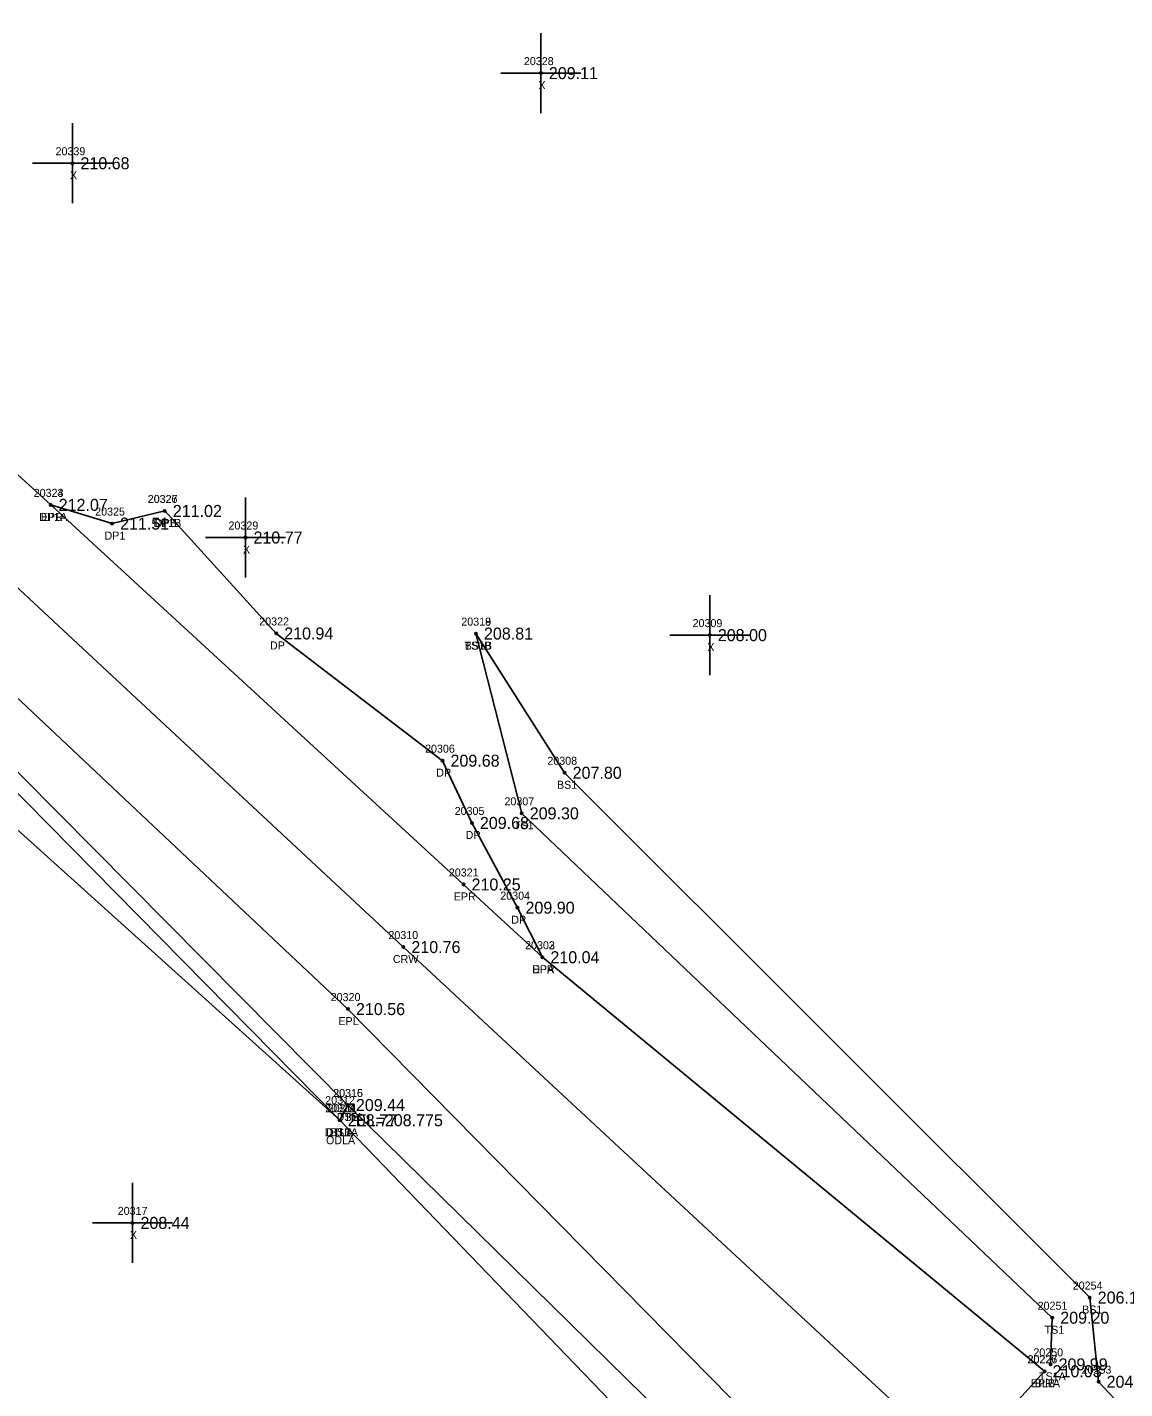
# Model space of a CAD drawing. Extents: x 2260230 to 2261304, y 1064626 to 1065587.
# Drawn here: x 2260344.2 to 2260481.3, y 1065386.5 to 1065556.6 of the extents above; entities that cross this region are included whole.
import ezdxf

# ---------------------------------------------------------------- set-up
doc = ezdxf.new("R2010")
doc.units = 0
for name, color, linetype in [('RD_DTM_BkLn1', 7, 'Continuous'), ('RD_DTM_BkLn2', 7, 'Continuous'), ('RD_DTM_BkLn_txCode', 7, 'Continuous'), ('RD_EX_Driveway', 7, 'Continuous'), ('RD_EX_Driveway_txCode', 7, 'Continuous'), ('RD_EX_H2O', 7, 'Continuous'), ('RD_EX_H2O_txCode', 7, 'Continuous'), ('RD_EX_Misc', 7, 'Continuous'), ('RD_EX_Misc_txCode', 7, 'Continuous'), ('RD_EX_Road', 7, 'Continuous'), ('RD_EX_Road_txCode', 7, 'Continuous'), ('RD_EX_TX_Driveway_ELEV', 7, 'Continuous'), ('RD_EX_TX_H2O_ELEV', 7, 'Continuous'), ('RD_EX_TX_Misc_ELEV', 7, 'Continuous'), ('RD_EX_TX_Road_ELEV', 7, 'Continuous'), ('RD_HC_Survey_ELEV', 7, 'Continuous'), ('RD_HC_Survey_txCode', 7, 'Continuous'), ('RD_SMD_Locator', 7, 'Continuous')]:
    doc.layers.add(name, color=color, linetype=linetype)

msp = doc.modelspace()

# ---------------------------------------------------------------- linework, layer by layer
at = {"layer": 'RD_DTM_BkLn1'}
for points in [[(2260460.75, 1065377.06), (2260391.17, 1065441.67), (2260322.55, 1065505.55), (2260275.44, 1065548.93)], [(2260450.76, 1065366.34), (2260460.75, 1065377.06), (2260471.29, 1065388.66)]]:
    msp.add_lwpolyline(points, dxfattribs=at)
at = {"layer": 'RD_DTM_BkLn2'}
for points in [[(2260472.04, 1065389.52), (2260472.25, 1065395.35), (2260405.96, 1065458.38), (2260400.24, 1065480.84)], [(2260484.22, 1065380.75), (2260478.04, 1065387.35), (2260476.93, 1065397.87), (2260411.32, 1065463.45), (2260400.24, 1065480.84)], [(2260448.41, 1065364.08), (2260444.54, 1065362.67), (2260384.24, 1065421.93)], [(2260459.63, 1065339.19), (2260441.77, 1065357.68), (2260430.08, 1065371.39), (2260383.23, 1065420.03)]]:
    msp.add_lwpolyline(points, dxfattribs=at)
at = {"layer": 'RD_EX_Driveway'}
for points in [[(2260347.1, 1065496.93), (2260354.77, 1065494.59), (2260361.36, 1065496.17)], [(2260408.54, 1065440.4), (2260405.43, 1065446.59), (2260399.73, 1065457.18), (2260396.06, 1065464.96), (2260375.28, 1065480.86), (2260361.36, 1065496.17)]]:
    msp.add_lwpolyline(points, dxfattribs=at)
at = {"layer": 'RD_EX_H2O'}
for points in [[(2260383.23, 1065420.03), (2260384.24, 1065421.93), (2260311.81, 1065494.98), (2260265.21, 1065536.25)], [(2260383.23, 1065420.03), (2260310.39, 1065493.94), (2260264.03, 1065534.75)], [(2260383.23, 1065420.03), (2260328.98, 1065468.86), (2260307.44, 1065488.32), (2260261.06, 1065532)]]:
    msp.add_lwpolyline(points, dxfattribs=at)
at = {"layer": 'RD_EX_Misc'}
for p, q in [((2260408.35, 1065545.88), (2260408.35, 1065555.88)), ((2260403.35, 1065550.88), (2260413.35, 1065550.88)), ((2260349.82, 1065534.62), (2260349.82, 1065544.62)), ((2260344.82, 1065539.62), (2260354.82, 1065539.62)), ((2260371.44, 1065487.85), (2260371.44, 1065497.85)), ((2260366.44, 1065492.85), (2260376.44, 1065492.85)), ((2260429.46, 1065475.65), (2260429.46, 1065485.65)), ((2260424.46, 1065480.65), (2260434.46, 1065480.65)), ((2260357.32, 1065402.2), (2260357.32, 1065412.2)), ((2260352.32, 1065407.2), (2260362.32, 1065407.2))]:
    msp.add_line(p, q, dxfattribs=at)
at = {"layer": 'RD_EX_Road'}
for points in [[(2260471.29, 1065388.66), (2260408.54, 1065440.4), (2260398.69, 1065449.49), (2260347.1, 1065496.93), (2260329.06, 1065513.35), (2260281.81, 1065556.62)], [(2260450.76, 1065366.34), (2260384.25, 1065433.92), (2260316.12, 1065498), (2260269.16, 1065540.98)]]:
    msp.add_lwpolyline(points, dxfattribs=at)
at = {"layer": 'RD_SMD_Locator'}
for centre in [(2260408.35, 1065550.88), (2260349.82, 1065539.62), (2260347.1, 1065496.93), (2260347.1, 1065496.93), (2260361.36, 1065496.17), (2260361.36, 1065496.17), (2260354.77, 1065494.59), (2260371.44, 1065492.85), (2260375.28, 1065480.86), (2260400.24, 1065480.84), (2260400.24, 1065480.84), (2260429.46, 1065480.65), (2260396.06, 1065464.96), (2260411.32, 1065463.45), (2260405.96, 1065458.38), (2260399.73, 1065457.18), (2260398.69, 1065449.49), (2260405.43, 1065446.59), (2260391.17, 1065441.67), (2260408.54, 1065440.4), (2260408.54, 1065440.4), (2260384.25, 1065433.92), (2260384.24, 1065421.93), (2260384.24, 1065421.93), (2260383.23, 1065420.03), (2260383.23, 1065420.03), (2260383.23, 1065420.03), (2260383.23, 1065420.03), (2260357.32, 1065407.2), (2260476.93, 1065397.87), (2260472.25, 1065395.35), (2260472.04, 1065389.52), (2260471.29, 1065388.66), (2260471.29, 1065388.66), (2260478.04, 1065387.35)]:
    msp.add_circle(centre, 0.15, dxfattribs=at)

# ---------------------------------------------------------------- texts
at = {"layer": 'RD_DTM_BkLn_txCode'}
for s, p in [('20318', (2260398.41, 1065481.84)), ('20319', (2260398.41, 1065481.84)), ('TS1B', (2260398.81, 1065478.84)), ('BS1B', (2260398.83, 1065478.84)), ('20308', (2260409.16, 1065464.45)), ('BS1', (2260410.37, 1065461.45)), ('20307', (2260403.8, 1065459.38)), ('TS1', (2260405, 1065456.38)), ('20315', (2260382.41, 1065422.93)), ('20311', (2260381.68, 1065421.03)), ('TSB', (2260382.98, 1065419.93)), ('BSB', (2260381.98, 1065418.03)), ('20254', (2260474.81, 1065398.87)), ('20251', (2260470.42, 1065396.35)), ('BS1', (2260475.98, 1065395.87)), ('TS1', (2260471.29, 1065393.35)), ('20250', (2260469.89, 1065390.52)), ('20226', (2260469.15, 1065389.66)), ('TS1A', (2260470.6, 1065387.52)), ('20253', (2260475.92, 1065388.35)), ('BLB', (2260470.07, 1065386.66))]:
    msp.add_text(s, height=1, dxfattribs=at).set_placement(p)
at = {"layer": 'RD_EX_Driveway_txCode'}
for s, p in [('20324', (2260344.98, 1065497.93)), ('20325', (2260352.66, 1065495.59)), ('20326', (2260359.22, 1065497.17)), ('20327', (2260359.24, 1065497.17)), ('DP1A', (2260345.67, 1065494.93)), ('DP1B', (2260359.94, 1065494.17)), ('DPB', (2260360.11, 1065494.17)), ('DP1', (2260353.83, 1065492.59)), ('20322', (2260373.16, 1065481.86)), ('DP', (2260374.5, 1065478.86)), ('20306', (2260393.88, 1065465.96)), ('DP', (2260395.28, 1065462.96)), ('20305', (2260397.58, 1065458.18)), ('DP', (2260398.95, 1065455.18)), ('20304', (2260403.28, 1065447.59)), ('DP', (2260404.65, 1065444.59)), ('20303', (2260406.38, 1065441.4)), ('DPA', (2260407.27, 1065438.4))]:
    msp.add_text(s, height=1, dxfattribs=at).set_placement(p)
at = {"layer": 'RD_EX_H2O_txCode'}
for s, p in [('20316', (2260382.39, 1065422.93)), ('20312', (2260381.4, 1065422.03)), ('20313', (2260381.4, 1065421.03)), ('20314', (2260381.4, 1065421.03)), ('DTL1', (2260382.83, 1065419.93)), ('DTL1A', (2260381.34, 1065418.03)), ('DTLA', (2260381.5, 1065418.03)), ('ODLA', (2260381.5, 1065417.03))]:
    msp.add_text(s, height=1, dxfattribs=at).set_placement(p)
at = {"layer": 'RD_EX_Misc_txCode'}
for s, p in [('20328', (2260406.23, 1065551.88)), ('X', (2260408.04, 1065548.88)), ('20339', (2260347.71, 1065540.62)), ('X', (2260349.51, 1065537.62)), ('20329', (2260369.32, 1065493.85)), ('X', (2260371.13, 1065490.85)), ('20309', (2260427.31, 1065481.65)), ('X', (2260429.15, 1065478.65)), ('20317', (2260355.48, 1065408.2)), ('X', (2260357, 1065405.2))]:
    msp.add_text(s, height=1, dxfattribs=at).set_placement(p)
at = {"layer": 'RD_EX_Road_txCode'}
for s, p in [('20323', (2260344.98, 1065497.93)), ('EPR', (2260345.87, 1065494.93)), ('20321', (2260396.85, 1065450.49)), ('EPR', (2260397.46, 1065447.49)), ('20302', (2260406.38, 1065441.4)), ('EPR', (2260407.31, 1065438.4)), ('20320', (2260382.09, 1065434.92)), ('EPL', (2260383.05, 1065431.92)), ('20227', (2260469.18, 1065389.66)), ('EPRA', (2260469.58, 1065386.66))]:
    msp.add_text(s, height=1, dxfattribs=at).set_placement(p)
at = {"layer": 'RD_EX_TX_Driveway_ELEV'}
for s, p in [('212.07', (2260348.1, 1065496.18)), ('211.02', (2260362.36, 1065495.42)), ('211.02', (2260362.36, 1065495.42)), ('211.51', (2260355.77, 1065493.84)), ('210.94', (2260376.28, 1065480.11)), ('209.68', (2260397.06, 1065464.21)), ('209.68', (2260400.73, 1065456.43)), ('209.90', (2260406.43, 1065445.84)), ('210.04', (2260409.54, 1065439.65))]:
    msp.add_text(s, height=1.5, dxfattribs=at).set_placement(p)
at = {"layer": 'RD_EX_TX_H2O_ELEV'}
for s, p in [('209.44', (2260385.24, 1065421.18)), ('208.77', (2260384.23, 1065419.28)), ('208.77', (2260384.23, 1065419.28)), ('EL=208.775', (2260385.23, 1065419.28))]:
    msp.add_text(s, height=1.5, dxfattribs=at).set_placement(p)
at = {"layer": 'RD_EX_TX_Misc_ELEV'}
for s, p in [('209.11', (2260409.35, 1065550.13)), ('210.68', (2260350.82, 1065538.87)), ('210.77', (2260372.44, 1065492.1)), ('208.81', (2260401.24, 1065480.09)), ('208.81', (2260401.24, 1065480.09)), ('208.00', (2260430.46, 1065479.9)), ('207.80', (2260412.32, 1065462.7)), ('209.30', (2260406.96, 1065457.63)), ('209.44', (2260385.24, 1065421.18)), ('208.77', (2260384.23, 1065419.28)), ('208.44', (2260358.32, 1065406.45)), ('206.12', (2260477.93, 1065397.12)), ('209.20', (2260473.25, 1065394.6)), ('210.03', (2260472.29, 1065387.91)), ('209.99', (2260473.04, 1065388.77)), ('204.79', (2260479.04, 1065386.6))]:
    msp.add_text(s, height=1.5, dxfattribs=at).set_placement(p)
at = {"layer": 'RD_EX_TX_Road_ELEV'}
for s, p in [('212.07', (2260348.1, 1065496.18)), ('210.25', (2260399.69, 1065448.74)), ('210.04', (2260409.54, 1065439.65)), ('210.56', (2260385.25, 1065433.17)), ('210.03', (2260472.29, 1065387.91))]:
    msp.add_text(s, height=1.5, dxfattribs=at).set_placement(p)
at = {"layer": 'RD_HC_Survey_ELEV'}
msp.add_text('210.76', height=1.5, dxfattribs=at).set_placement((2260392.17, 1065440.92))
at = {"layer": 'RD_HC_Survey_txCode'}
for s, p in [('20310', (2260389.3, 1065442.67)), ('CRW', (2260389.86, 1065439.67))]:
    msp.add_text(s, height=1, dxfattribs=at).set_placement(p)

doc.saveas('drawing.dxf')
